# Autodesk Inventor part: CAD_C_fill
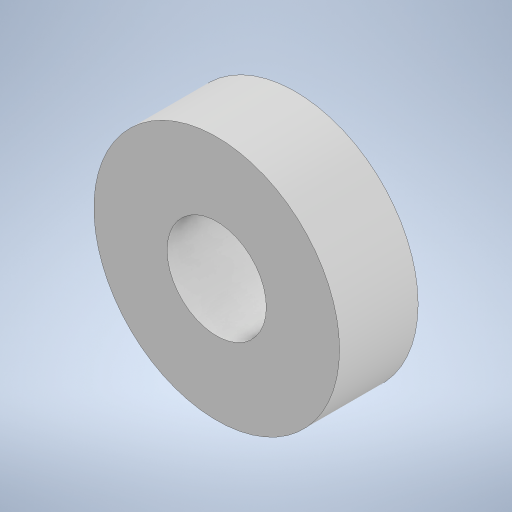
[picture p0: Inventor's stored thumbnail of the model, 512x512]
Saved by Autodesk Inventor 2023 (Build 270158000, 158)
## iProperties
Created: 2023-05
Part Number: CAD_C_fill
Material: Generic
Document SubType Name: Modeling
Designer: steff
Density: 1 g/cm^3
Appearance: Default
Author: steff
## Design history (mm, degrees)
sketch "Sketch1"
  geometry: C1 r 5.05 at (0, 0); C2 r 12.5 at (0, 0); 1 further point
  constraints: 2 centre point, 2 coincident
  dimensions: "d0" = 10.1 diameter of C1; "d1" = 25 diameter of C2
extrude "Extrusion1" new body sketch "Sketch1" distance "d2" = 8; taper "d3" = 0 deg
body "Solid1"
